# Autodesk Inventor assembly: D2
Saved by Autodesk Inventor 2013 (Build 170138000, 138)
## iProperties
Created: 2021-02
Part Number: D2
Document SubType Name: Assembly
Designer: Fede
Author: Fede
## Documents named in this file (2)
- C:\0000 FEDE\16GB\0000 INTERIOR\DE_TMP_BAS\BAS_DTON - demora conexion al energizar\DTON_MANUAL\img\INVENTOR\BAS_DTON - SIN R\D2.iam
- C:\0000 FEDE\16GB\0000 INTERIOR\DE_TMP_BAS\BAS_DTON - demora conexion al energizar\DTON_MANUAL\img\INVENTOR\BAS_DTON - SIN R\sod123.iam
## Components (1 placed, 1 different names)
1. sod123:1 [sub-assembly]
